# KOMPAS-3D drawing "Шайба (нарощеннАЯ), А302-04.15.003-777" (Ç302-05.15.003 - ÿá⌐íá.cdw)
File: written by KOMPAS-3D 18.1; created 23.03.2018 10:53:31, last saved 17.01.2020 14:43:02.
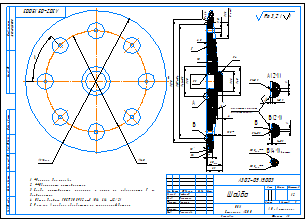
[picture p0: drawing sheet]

Sheet 1: A3, landscape

Document properties: Автор: Милов; Параметр неуказанной шероховатости: Ra 3,2; Полное имя файла: ..\3Д ПВХ\А302-01.15.003 - Шайба.m3d; Организация: Милов

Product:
- Part/product: Шайба (нарощеннАЯ)  | designation А302-04.15.003-777
    Материал: Полипропилен  ГОСТ 26996-86 (density 900 kg/m3)
    Масса: 0.433016
    Раздел спецификации: Детали
    Форматы листов документа: A4
    source file: ..\А302-04.00.000 - Мембранный насос ASTRA-302-PP\А302-04.15.003-777 - Шайба.cdw
- Part/product: Шайба  | designation А302-02.15.003
    Материал: Полипропилен  ГОСТ 26996-86 (density 900 kg/m3)
    Масса: 0.251914
    Раздел спецификации: Детали
    Форматы листов документа: A4
- Part/product: Шайба  | designation А302-01.15.003
    Масса: 0.292092
    Раздел спецификации: Детали
    Форматы листов документа: A4
- Part/product: Шайба  | designation А302-03.15.003
    Материал: Полипропилен  ГОСТ 26996-86 (density 900 kg/m3)
    Масса: 0.28231
    Раздел спецификации: Детали
    Форматы листов документа: A4
    source file: ..\Чертежи Полипропилен\А302-03.15.003 - Шайба.cdw
- Part/product: Шайба  | designation А302-05.15.003
    Материал: Поливинилхлорид (density 0 kg/m3)
    Раздел спецификации: Детали
    Форматы листов документа: A4
    source file: ..\А302-04.00.000 - Мембранный насос ASTRA-302-PP\А302-04.15.003 - Шайба.cdw, ..\Чертежи ПВХ\А302-02.15.003 - Шайба.cdw, ..\Чертежи Полипропилен\А302-03.15.003 - Шайба.cdw
- Part/product: Шайба  | designation А302-04.15.003
    Материал: Полипропилен  ГОСТ 26996-86 (density 900 kg/m3)
    Масса: 0.247573
    Раздел спецификации: Детали
    Форматы листов документа: A4

Title block, sheet 1: Наименование: Шайба; designation: А302-05.15.003; Материал: ПВХ / Стержень  200; scale: 1:2; Количество листов документа: 1; organisation: АО «Астерион»; Форматы листов документа: A3; stored path: \\192.168.87.28\Konstructor_doc\Мембранные насосы\Мембранный электропривод\А302-00.00.000 - ASTRA-302 (МЭ200)\Чертежи\А302-00.15.003 - Шайба.cdw; Разработал: Лифлянд; Проверил: Борисенко; Т. контр.: Лучихин; Утвердил: Григорьева

Views: Вид 1, Местный разрез 1, Спереди, Выносной элемент 3, Выносной элемент 4, Выносной элемент 5, Выносной элемент А, Выносной элемент, Выносной элемент Б, Выносной элемент В
Referenced files in D:\Мембранные насосы\Мембранный электропривод\А302-00.00.000 - ASTRA-302 (МЭ200)\3Д ПВХ\: А302-01.15.003 - Шайба.m3d
Referenced files in Z:\Мембранные насосы\Мембранный электропривод\А302-00.00.000 - ASTRA-302 (МЭ200)\3Д\: А302-00.15.003 - Шайба.m3d
Referenced files in Z:\Мембранные насосы\Мембранный электропривод\А302-00.00.000 - ASTRA-302 (МЭ200)\3Д ПВХ\: А302-01.15.003 - Шайба.m3d
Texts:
  Ra 1,6
  Зона контакта с мембраной
  поверхность глянцевая
  Ra 0,80
  Ra 3,2
  Ra 3,2 ( )
Dimensions and other numbers on the sheet: 6,5; 40; 28; 4; 6; 20; 3; 10; 13,5; 41±0,3; 157±0,4; 7; 170; 2; 5; 23; 8 отв.; 21; 1±0,1; 0,5; 1:2

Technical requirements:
  *Размеры для справок.
  **Обеспечить инструментом.
  Следы инструмента, царапины и риски на поверхности  Г  не
  допускаются.
  Общие допуски ГОСТ 30893.2-mK (H14, h14,  t2/2).
  Размеры в скобках обработать по сопрягаемой детали.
